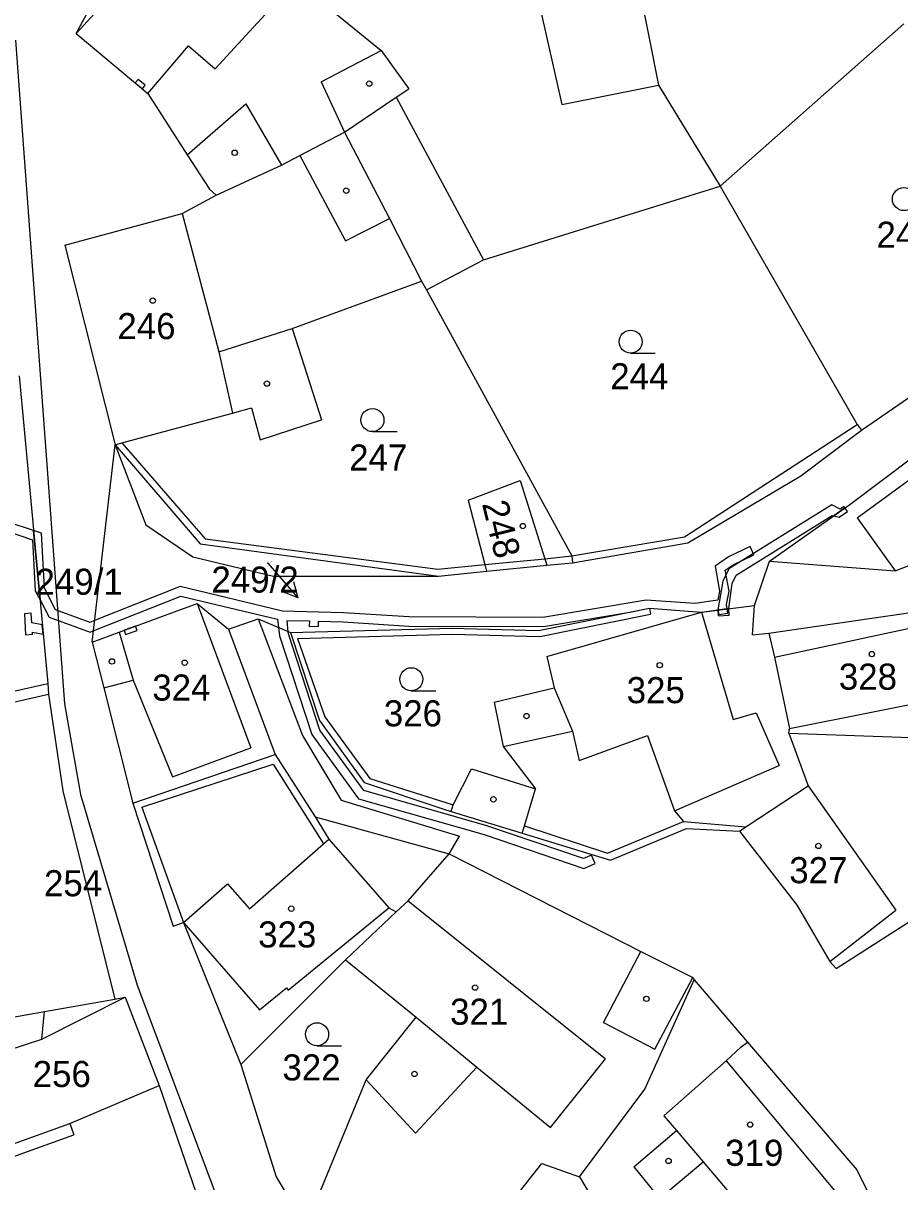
# Model space of a CAD drawing. Extents: x -785744 to -782822, y -1067550 to -1063910.
# Drawn here: x -783849.7 to -783792.6, y -1065395.6 to -1065320.1 of the extents above; entities that cross this region are included whole.
import ezdxf

# ---------------------------------------------------------------- set-up
doc = ezdxf.new("R2010")
doc.units = 0
for name, color, linetype in [('Hranice parcel', 7, 'Continuous'), ('Parcelní čísla', 7, 'Continuous'), ('Pop_ČP_popisy', 7, 'Continuous'), ('Vnitřní kresba', 7, 'Continuous'), ('Věcná břemena k části', 7, 'Continuous'), ('Značky budov', 7, 'Continuous'), ('Značky kultur', 7, 'Continuous')]:
    doc.layers.add(name, color=color, linetype=linetype)

msp = doc.modelspace()

# ---------------------------------------------------------------- linework, layer by layer
at = {"layer": 'Hranice parcel'}
for points in [[(-783846.27, -1065320.75), (-783838.02, -1065311.75)], [(-783810.28, -1065314.14), (-783808.3, -1065324.12)], [(-783831.94, -1065317.32), (-783826.39, -1065321.85)], [(-783804.29, -1065330.7), (-783792.31, -1065320.13)], [(-783846.27, -1065320.75), (-783841.59, -1065324.66)], [(-783830.3, -1065323.9), (-783826.39, -1065321.85)], [(-783830.3, -1065323.9), (-783828.78, -1065327.19)], [(-783841.59, -1065324.66), (-783839.02, -1065328.67)], [(-783808.3, -1065324.12), (-783804.29, -1065330.7)], [(-783831.68, -1065328.7), (-783828.78, -1065327.19)], [(-783828.78, -1065327.19), (-783825.85, -1065332.81)], [(-783839.02, -1065328.67), (-783837.57, -1065330.9)], [(-783837.13, -1065331.29), (-783832.88, -1065329.33)], [(-783832.88, -1065329.33), (-783831.68, -1065328.7)], [(-783819.71, -1065335.52), (-783804.29, -1065330.7)], [(-783804.29, -1065330.7), (-783795.35, -1065346.25)], [(-783839.36, -1065332.49), (-783837.13, -1065331.29)], [(-783837.57, -1065330.9), (-783837.13, -1065331.29)], [(-783847, -1065334.56), (-783839.36, -1065332.49)], [(-783825.85, -1065332.81), (-783823.75, -1065336.9)], [(-783847, -1065334.56), (-783843.73, -1065347.57)], [(-783823.43, -1065337.46), (-783819.71, -1065335.52)], [(-783832.18, -1065339.98), (-783823.75, -1065336.9)], [(-783823.75, -1065336.9), (-783823.43, -1065337.46)], [(-783795.08, -1065346.62), (-783780.58, -1065336.63)], [(-783823.43, -1065337.46), (-783813.95, -1065354.82)], [(-783832.18, -1065339.98), (-783830.28, -1065345.94)], [(-783795.84, -1065351.46), (-783783.28, -1065342.01)], [(-783849.99, -1065343.07), (-783848.11, -1065363.14)], [(-783836.08, -1065345.5), (-783834.83, -1065345.16)], [(-783834.83, -1065345.16), (-783834.26, -1065347.24)], [(-783843.29, -1065347.44), (-783836.08, -1065345.5)], [(-783834.26, -1065347.24), (-783830.28, -1065345.94)], [(-783799.03, -1065349.59), (-783795.08, -1065346.62)], [(-783795.35, -1065346.25), (-783795.08, -1065346.62)], [(-783843.73, -1065347.57), (-783843.29, -1065347.44)], [(-783845.23, -1065360.44), (-783843.73, -1065347.57)], [(-783843.73, -1065347.57), (-783838.18, -1065354.02)], [(-783843.73, -1065347.57), (-783841.73, -1065352.79)], [(-783806.39, -1065353.97), (-783799.03, -1065349.59)], [(-783820.72, -1065351.18), (-783817.32, -1065349.91)], [(-783817.32, -1065349.91), (-783815.72, -1065355)], [(-783820.72, -1065351.18), (-783819.62, -1065355.37)], [(-783801.06, -1065355.17), (-783795.84, -1065351.46)], [(-783841.73, -1065352.79), (-783838.66, -1065354.88)], [(-783838.18, -1065354.02), (-783822.64, -1065356.14)], [(-783813.91, -1065355.27), (-783806.39, -1065353.97)], [(-783792.88, -1065355.8), (-783788.73, -1065354.19)], [(-783838.66, -1065354.88), (-783833.39, -1065356.13)], [(-783815.72, -1065355), (-783815.58, -1065355.43)], [(-783813.95, -1065354.82), (-783813.91, -1065355.27)], [(-783819.62, -1065355.37), (-783819.51, -1065355.81)], [(-783819.51, -1065355.81), (-783815.58, -1065355.43)], [(-783815.58, -1065355.43), (-783813.91, -1065355.27)], [(-783802.04, -1065358.04), (-783801.06, -1065355.17)], [(-783801.06, -1065355.17), (-783792.88, -1065355.8)], [(-783833.39, -1065356.13), (-783822.64, -1065356.14)], [(-783822.64, -1065356.14), (-783819.51, -1065355.81)], [(-783843.47, -1065359.78), (-783838.37, -1065357.92)], [(-783838.37, -1065357.92), (-783836.34, -1065359.59)], [(-783805.5, -1065358.48), (-783802.04, -1065358.04)], [(-783802.18, -1065359.97), (-783802.04, -1065358.04)], [(-783816.13, -1065359.69), (-783808.9, -1065358.23)], [(-783815.59, -1065361.37), (-783805.5, -1065358.48)], [(-783808.9, -1065358.23), (-783805.5, -1065358.48)], [(-783801.11, -1065359.86), (-783789.03, -1065358.1)], [(-783836.34, -1065359.59), (-783834.4, -1065358.91)], [(-783834.4, -1065358.91), (-783832.29, -1065359.82)], [(-783832.29, -1065359.82), (-783821.78, -1065359.52)], [(-783821.78, -1065359.52), (-783816.13, -1065359.69)], [(-783845.23, -1065360.44), (-783843.47, -1065359.78)], [(-783836.34, -1065359.59), (-783833.3, -1065367.77)], [(-783832.29, -1065359.82), (-783830.41, -1065365.56)], [(-783802.18, -1065359.97), (-783801.11, -1065359.86)], [(-783801.11, -1065359.86), (-783800.75, -1065361.42)], [(-783845.23, -1065360.44), (-783844.46, -1065363.41)], [(-783815.59, -1065361.37), (-783815.1, -1065363.43)], [(-783800.75, -1065361.42), (-783799.76, -1065366.08)], [(-783848.11, -1065363.14), (-783848.06, -1065363.84)], [(-783854.85, -1065365.37), (-783848.06, -1065363.84)], [(-783848.06, -1065363.84), (-783847.14, -1065370.13)], [(-783844.46, -1065363.41), (-783842.56, -1065370.93)], [(-783819.01, -1065364.36), (-783815.1, -1065363.43)], [(-783819.01, -1065364.36), (-783818.42, -1065367.25)], [(-783830.41, -1065365.56), (-783827.48, -1065369.59)], [(-783799.82, -1065366.38), (-783799.76, -1065366.08)], [(-783799.82, -1065366.38), (-783798.56, -1065369.81)], [(-783799.82, -1065366.38), (-783787.6, -1065366.8)], [(-783842.56, -1065370.93), (-783833.3, -1065367.77)], [(-783833.3, -1065367.77), (-783830.69, -1065371.84)], [(-783818.42, -1065367.25), (-783816.32, -1065370.01)], [(-783821.69, -1065371.05), (-783820.5, -1065368.71)], [(-783820.5, -1065368.71), (-783816.32, -1065370.01)], [(-783847.14, -1065370.13), (-783843.75, -1065383.73)], [(-783827.48, -1065369.59), (-783822.3, -1065371.34)], [(-783802.61, -1065372.48), (-783798.56, -1065369.81)], [(-783842.56, -1065370.93), (-783839.94, -1065378.96)], [(-783822.3, -1065371.34), (-783821.82, -1065371.48)], [(-783821.82, -1065371.48), (-783821.69, -1065371.05)], [(-783821.82, -1065371.48), (-783817.2, -1065372.89)], [(-783830.69, -1065371.84), (-783829.8, -1065373.29)], [(-783817.2, -1065372.89), (-783811.44, -1065374.66)], [(-783811.44, -1065374.66), (-783806.49, -1065372.6)], [(-783806.49, -1065372.6), (-783803.03, -1065372.76)], [(-783803.03, -1065372.76), (-783802.61, -1065372.48)], [(-783803.03, -1065372.76), (-783799.27, -1065377.62)], [(-783829.8, -1065373.29), (-783825.88, -1065377.76)], [(-783824.63, -1065377.3), (-783821.94, -1065374.25)], [(-783821.94, -1065374.25), (-783809.46, -1065380.62)], [(-783825.4, -1065378.03), (-783824.63, -1065377.3)], [(-783799.27, -1065377.62), (-783797.14, -1065381.27)], [(-783828.7, -1065381.16), (-783825.4, -1065378.03)], [(-783825.88, -1065377.76), (-783825.4, -1065378.03)], [(-783796.72, -1065381.73), (-783791.22, -1065378.19)], [(-783839.94, -1065378.96), (-783839.27, -1065378.72)], [(-783839.27, -1065378.72), (-783835.52, -1065387.99)], [(-783809.46, -1065380.62), (-783806.07, -1065382.3)], [(-783835.52, -1065387.99), (-783828.7, -1065381.16)], [(-783828.7, -1065381.16), (-783824.11, -1065384.9)], [(-783797.14, -1065381.27), (-783796.72, -1065381.73)], [(-783809.19, -1065389.59), (-783805.99, -1065382.45)], [(-783806.07, -1065382.3), (-783805.99, -1065382.45)], [(-783805.99, -1065382.45), (-783802.5, -1065386.52)], [(-783848.32, -1065384.53), (-783843.75, -1065383.73)], [(-783843.75, -1065383.73), (-783843.06, -1065383.6)], [(-783843.06, -1065383.6), (-783840.85, -1065389.36)], [(-783851.39, -1065385.06), (-783848.32, -1065384.53)], [(-783848.51, -1065386.33), (-783848.32, -1065384.53)], [(-783827.35, -1065388.98), (-783824.11, -1065384.9)], [(-783852.98, -1065387.78), (-783848.51, -1065386.33)], [(-783802.92, -1065386.84), (-783802.5, -1065386.52)], [(-783802.5, -1065386.52), (-783795.38, -1065394.86)], [(-783803.9, -1065387.75), (-783802.92, -1065386.84)], [(-783835.52, -1065387.99), (-783833.22, -1065395.31)], [(-783803.9, -1065387.75), (-783796.83, -1065396.2)], [(-783831.29, -1065398.55), (-783827.35, -1065388.98)], [(-783846.68, -1065391.83), (-783840.85, -1065389.36)], [(-783840.85, -1065389.36), (-783837.73, -1065398.45)], [(-783813.46, -1065395.3), (-783809.19, -1065389.59)], [(-783846.68, -1065391.83), (-783846.41, -1065392.56)], [(-783850.7, -1065394.11), (-783846.41, -1065392.56)], [(-783808.23, -1065396.72), (-783805.4, -1065394.32)], [(-783805.4, -1065394.32), (-783800.95, -1065399.58)], [(-783818.16, -1065397.3), (-783815.9, -1065394.43)], [(-783815.9, -1065394.43), (-783813.46, -1065395.3)], [(-783795.38, -1065394.86), (-783791.41, -1065402.84)], [(-783833.22, -1065395.31), (-783831.29, -1065398.55)], [(-783813.46, -1065395.3), (-783809.83, -1065401.41)]]:
    msp.add_lwpolyline(points, dxfattribs=at)
at = {"layer": 'Pop_ČP_popisy'}
msp.add_line((-783833.78, -1065355.3), (-783831.806, -1065357.559), dxfattribs=at)
for points in [[(-783833.82, -1065355.26), (-783833.78, -1065355.3)], [(-783832.087, -1065356.477), (-783831.806, -1065357.559), (-783832.84, -1065357.135)]]:
    msp.add_lwpolyline(points, dxfattribs=at)
at = {"layer": 'Vnitřní kresba'}
for points in [[(-783816.82, -1065315.53), (-783814.61, -1065325.37)], [(-783837.2, -1065323.06), (-783831.94, -1065317.32)], [(-783846.27, -1065320.75), (-783844.85, -1065318.11)], [(-783850.22, -1065321.18), (-783847.02, -1065364.46)], [(-783841.59, -1065324.66), (-783838.94, -1065321.56)], [(-783838.94, -1065321.56), (-783837.2, -1065323.06)], [(-783826.39, -1065321.85), (-783824.58, -1065324.35)], [(-783825.4, -1065324.91), (-783824.58, -1065324.35)], [(-783814.61, -1065325.37), (-783808.3, -1065324.12)], [(-783839.02, -1065328.67), (-783835.21, -1065325.33)], [(-783835.21, -1065325.33), (-783832.88, -1065329.33)], [(-783828.78, -1065327.19), (-783825.4, -1065324.91)], [(-783825.4, -1065324.91), (-783819.71, -1065335.52)], [(-783831.68, -1065328.7), (-783828.71, -1065334.28)], [(-783839.36, -1065332.49), (-783837.43, -1065339.76)], [(-783828.71, -1065334.28), (-783825.85, -1065332.81)], [(-783837.43, -1065339.76), (-783836.96, -1065341.5)], [(-783836.96, -1065341.5), (-783832.18, -1065339.98)], [(-783836.96, -1065341.5), (-783836.08, -1065345.5)], [(-783795.35, -1065352.34), (-783783.09, -1065343.37)], [(-783806.61, -1065353.58), (-783795.35, -1065346.25)], [(-783843.29, -1065347.44), (-783837.85, -1065353.71)], [(-783795.35, -1065352.34), (-783792.88, -1065355.8)], [(-783837.85, -1065353.71), (-783822.68, -1065355.69)], [(-783813.95, -1065354.82), (-783806.61, -1065353.58)], [(-783819.62, -1065355.37), (-783815.72, -1065355)], [(-783815.72, -1065355), (-783813.95, -1065354.82)], [(-783822.68, -1065355.69), (-783819.62, -1065355.37)], [(-783838.37, -1065357.92), (-783834.87, -1065367.33)], [(-783816.05, -1065360.08), (-783808.82, -1065358.62)], [(-783808.9, -1065358.23), (-783808.82, -1065358.62)], [(-783805.5, -1065358.48), (-783803.44, -1065365.49)], [(-783834.4, -1065358.91), (-783831.5, -1065366.52)], [(-783800.75, -1065361.42), (-783789.9, -1065359.1)], [(-783843.47, -1065359.78), (-783842.54, -1065362.92)], [(-783831.83, -1065360.2), (-783821.76, -1065359.91)], [(-783831.83, -1065360.2), (-783830.05, -1065365.3)], [(-783821.76, -1065359.91), (-783816.05, -1065360.08)], [(-783863.39, -1065366.57), (-783848.11, -1065363.14)], [(-783844.46, -1065363.41), (-783842.54, -1065362.92)], [(-783842.54, -1065362.92), (-783839.98, -1065369.22)], [(-783815.1, -1065363.43), (-783813.9, -1065366.24)], [(-783799.76, -1065366.08), (-783788.86, -1065363.9)], [(-783847.02, -1065364.46), (-783845.98, -1065370.38)], [(-783830.05, -1065365.3), (-783827.12, -1065369.33)], [(-783803.44, -1065365.49), (-783801.94, -1065365.05)], [(-783801.94, -1065365.05), (-783800.44, -1065368.48)], [(-783818.42, -1065367.25), (-783813.9, -1065366.24)], [(-783813.9, -1065366.24), (-783813.48, -1065368.15)], [(-783831.5, -1065366.52), (-783828.99, -1065370.74)], [(-783813.48, -1065368.15), (-783809.03, -1065366.53)], [(-783809.03, -1065366.53), (-783807.26, -1065371.44)], [(-783839.98, -1065369.22), (-783834.87, -1065367.33)], [(-783841.98, -1065371.21), (-783833.43, -1065368.39)], [(-783833.43, -1065368.39), (-783830.14, -1065373.59)], [(-783807.26, -1065371.44), (-783800.44, -1065368.48)], [(-783827.12, -1065369.33), (-783821.69, -1065371.05)], [(-783817.05, -1065372.42), (-783816.32, -1065370.01)], [(-783798.56, -1065369.81), (-783792.84, -1065377.92)], [(-783845.98, -1065370.38), (-783842.28, -1065382.81)], [(-783828.99, -1065370.74), (-783821.27, -1065373.09)], [(-783841.98, -1065371.21), (-783839.27, -1065378.72)], [(-783807.26, -1065371.44), (-783806.68, -1065372.13)], [(-783830.69, -1065371.84), (-783821.94, -1065374.25)], [(-783817.2, -1065372.89), (-783817.05, -1065372.42)], [(-783817.05, -1065372.42), (-783811.63, -1065374.19)], [(-783811.63, -1065374.19), (-783806.68, -1065372.13)], [(-783806.68, -1065372.13), (-783802.61, -1065372.48)], [(-783821.94, -1065374.25), (-783821.27, -1065373.09)], [(-783834.96, -1065377.82), (-783830.14, -1065373.59)], [(-783830.14, -1065373.59), (-783829.8, -1065373.29)], [(-783839.27, -1065378.72), (-783836.41, -1065376.19)], [(-783836.41, -1065376.19), (-783834.96, -1065377.82)], [(-783824.63, -1065377.3), (-783811.76, -1065387.61)], [(-783832.44, -1065383.13), (-783825.88, -1065377.76)], [(-783797.14, -1065381.27), (-783792.84, -1065377.92)], [(-783839.27, -1065378.72), (-783834.31, -1065384.41)], [(-783811.88, -1065385.24), (-783809.46, -1065380.62)], [(-783842.28, -1065382.81), (-783836.83, -1065397.33)], [(-783834.31, -1065384.41), (-783832.56, -1065382.98)], [(-783832.56, -1065382.98), (-783832.44, -1065383.13)], [(-783808.55, -1065386.99), (-783806.07, -1065382.3)], [(-783848.51, -1065386.33), (-783843.06, -1065383.6)], [(-783824.11, -1065384.9), (-783820.14, -1065388.15)], [(-783811.88, -1065385.24), (-783808.55, -1065386.99)], [(-783824.15, -1065392.45), (-783820.14, -1065388.15)], [(-783820.14, -1065388.15), (-783815.34, -1065392.08)], [(-783815.34, -1065392.08), (-783811.76, -1065387.61)], [(-783807.95, -1065391.33), (-783803.9, -1065387.75)], [(-783827.35, -1065388.98), (-783824.15, -1065392.45)], [(-783850.96, -1065393.37), (-783846.68, -1065391.83)], [(-783807.95, -1065391.33), (-783807.13, -1065392.28)], [(-783809.92, -1065394.65), (-783807.13, -1065392.28)], [(-783807.13, -1065392.28), (-783805.4, -1065394.32)], [(-783809.92, -1065394.65), (-783808.23, -1065396.72)]]:
    msp.add_lwpolyline(points, dxfattribs=at)
at = {"layer": 'Věcná břemena k části'}
for points in [[(-783842.22, -1065323.74), (-783842.41, -1065323.97), (-783841.95, -1065324.36)], [(-783841.95, -1065324.36), (-783841.76, -1065324.13), (-783842.22, -1065323.74)], [(-783797, -1065351.48), (-783803.71, -1065355.65)], [(-783796.47, -1065351.77), (-783797, -1065351.48)], [(-783796.15, -1065351.68), (-783796.88, -1065352.2)], [(-783796.88, -1065352.2), (-783796.15, -1065351.68)], [(-783796.52, -1065352.28), (-783795.99, -1065351.93)], [(-783796.21, -1065351.6), (-783796.47, -1065351.77)], [(-783796.15, -1065351.68), (-783796.21, -1065351.6)], [(-783795.99, -1065351.93), (-783796.15, -1065351.68)], [(-783849.05, -1065353.16), (-783850.63, -1065352.63)], [(-783803.24, -1065356.07), (-783796.98, -1065352.18)], [(-783796.98, -1065352.18), (-783796.88, -1065352.2)], [(-783796.88, -1065352.2), (-783796.52, -1065352.28)], [(-783850.83, -1065353.19), (-783849.1, -1065353.77)], [(-783848.62, -1065357.68), (-783849.05, -1065353.16)], [(-783848.52, -1065353.33), (-783849.05, -1065353.16)], [(-783849.05, -1065353.16), (-783848.62, -1065357.68)], [(-783848.33, -1065356.93), (-783848.52, -1065353.33)], [(-783849.1, -1065353.77), (-783848.93, -1065357.09)], [(-783802.34, -1065354.21), (-783803.74, -1065354.87)], [(-783802.08, -1065354.75), (-783802.34, -1065354.21)], [(-783803.74, -1065354.87), (-783804.61, -1065355.49)], [(-783803.44, -1065355.39), (-783802.08, -1065354.75)], [(-783804.61, -1065355.49), (-783804.32, -1065357.12)], [(-783803.71, -1065355.65), (-783804.11, -1065356.47)], [(-783803.95, -1065355.75), (-783803.44, -1065355.39)], [(-783803.7, -1065357.12), (-783803.95, -1065355.75)], [(-783804.11, -1065356.47), (-783804.44, -1065358.34), (-783803.71, -1065358.25)], [(-783803.51, -1065356.61), (-783803.24, -1065356.07)], [(-783848.93, -1065357.09), (-783848.62, -1065357.68)], [(-783847.61, -1065358.33), (-783848.33, -1065356.93)], [(-783839.49, -1065356.82), (-783845.07, -1065359.03)], [(-783832.81, -1065358.41), (-783839.49, -1065356.82)], [(-783804.32, -1065357.12), (-783804.44, -1065357.7)], [(-783803.88, -1065357.98), (-783803.7, -1065357.12)], [(-783803.71, -1065358.25), (-783803.51, -1065356.61)], [(-783848.62, -1065357.68), (-783848.03, -1065358.81)], [(-783845.15, -1065359.71), (-783839.45, -1065357.44)], [(-783839.45, -1065357.44), (-783833.13, -1065358.95)], [(-783809.1, -1065357.7), (-783815.84, -1065358.83)], [(-783805.93, -1065357.91), (-783809.1, -1065357.7)], [(-783804.44, -1065357.7), (-783805.93, -1065357.91)], [(-783803.83, -1065358.27), (-783803.88, -1065357.98)], [(-783849.15, -1065359.17), (-783849.19, -1065358.56), (-783849.64, -1065358.59)], [(-783849.64, -1065358.59), (-783849.56, -1065359.96), (-783849.11, -1065359.93)], [(-783848.03, -1065358.81), (-783845.35, -1065359.79)], [(-783845.35, -1065359.15), (-783847.61, -1065358.33)], [(-783828.84, -1065358.52), (-783832.81, -1065358.41)], [(-783824.57, -1065358.8), (-783828.84, -1065358.52)], [(-783815.84, -1065358.83), (-783824.57, -1065358.8)], [(-783815.8, -1065359.43), (-783810.18, -1065358.49)], [(-783810.18, -1065358.49), (-783808.9, -1065358.23)], [(-783808.9, -1065358.23), (-783805.5, -1065358.48)], [(-783805.5, -1065358.48), (-783804.44, -1065358.34)], [(-783804.16, -1065358.31), (-783804.44, -1065358.34)], [(-783804.16, -1065358.31), (-783804.44, -1065358.34)], [(-783804.44, -1065358.34), (-783804.16, -1065358.31)], [(-783804.44, -1065358.34), (-783804.42, -1065358.73)], [(-783804.44, -1065358.34), (-783804.38, -1065358.64)], [(-783804.42, -1065358.73), (-783803.69, -1065358.69)], [(-783804.38, -1065358.64), (-783803.78, -1065358.56)], [(-783803.71, -1065358.25), (-783804.16, -1065358.31)], [(-783803.83, -1065358.27), (-783804.16, -1065358.31)], [(-783804.16, -1065358.31), (-783803.83, -1065358.27)], [(-783803.78, -1065358.56), (-783803.83, -1065358.27)], [(-783803.69, -1065358.69), (-783803.71, -1065358.25)], [(-783848.41, -1065359.93), (-783848.47, -1065359.31), (-783849.15, -1065359.17)], [(-783845.07, -1065359.03), (-783845.35, -1065359.15)], [(-783842.39, -1065359.39), (-783843.14, -1065359.66)], [(-783842.29, -1065359.67), (-783842.39, -1065359.39)], [(-783833.13, -1065358.95), (-783833.07, -1065359.48)], [(-783833.07, -1065359.48), (-783833.02, -1065360.02)], [(-783832.52, -1065359.02), (-783831.06, -1065359.06)], [(-783832.44, -1065359.76), (-783832.52, -1065359.02)], [(-783831.06, -1065359.06), (-783831.07, -1065359.42)], [(-783831.07, -1065359.42), (-783830.47, -1065359.4)], [(-783830.47, -1065359.4), (-783830.46, -1065359.08)], [(-783830.46, -1065359.08), (-783828.86, -1065359.12)], [(-783828.86, -1065359.12), (-783824.59, -1065359.4)], [(-783824.59, -1065359.4), (-783815.8, -1065359.43)], [(-783849.11, -1065359.93), (-783849.12, -1065359.79), (-783848.41, -1065359.93)], [(-783845.35, -1065359.79), (-783845.15, -1065359.71)], [(-783843.14, -1065359.66), (-783843.04, -1065359.94)], [(-783843.04, -1065359.94), (-783842.29, -1065359.67)], [(-783833.02, -1065360.02), (-783830.91, -1065366.47)], [(-783832.42, -1065359.9), (-783832.44, -1065359.76)], [(-783830.37, -1065366.19), (-783832.42, -1065359.9)], [(-783827.51, -1065370.11), (-783830.37, -1065366.19)], [(-783830.91, -1065366.47), (-783827.85, -1065370.66)], [(-783819.49, -1065372.41), (-783827.51, -1065370.11)], [(-783827.85, -1065370.66), (-783819.67, -1065372.99)], [(-783813.2, -1065374.55), (-783819.49, -1065372.41)], [(-783819.67, -1065372.99), (-783813.18, -1065375.19)], [(-783812.67, -1065374.33), (-783813.2, -1065374.55)], [(-783812.44, -1065374.88), (-783812.67, -1065374.33)], [(-783813.18, -1065375.19), (-783812.44, -1065374.88)]]:
    msp.add_lwpolyline(points, dxfattribs=at)
at = {"layer": 'Značky budov'}
for centre in [(-783827.16, -1065324.02), (-783835.93, -1065328.53), (-783828.66, -1065331), (-783841.27, -1065338.17), (-783833.83, -1065343.58), (-783817.15, -1065352.87), (-783794.4, -1065361.22), (-783843.93, -1065361.7), (-783839.19, -1065361.78), (-783808.22, -1065361.94), (-783816.91, -1065365.26), (-783819.07, -1065370.69), (-783797.88, -1065373.73), (-783832.24, -1065377.82), (-783820.26, -1065382.97), (-783809.09, -1065383.7), (-783824.21, -1065388.6), (-783802.33, -1065391.9), (-783807.65, -1065394.27)]:
    msp.add_circle(centre, 0.175, dxfattribs=at)
at = {"layer": 'Značky kultur'}
for p, q in [((-783810.12, -1065341.6), (-783808.52, -1065341.6)), ((-783826.95, -1065346.71), (-783825.35, -1065346.71)), ((-783824.42, -1065363.61), (-783822.82, -1065363.61)), ((-783830.56, -1065386.76), (-783828.96, -1065386.76))]:
    msp.add_line(p, q, dxfattribs=at)
for centre in [(-783792.31, -1065331.55), (-783810.12, -1065340.85), (-783826.95, -1065345.96), (-783824.42, -1065362.86), (-783830.56, -1065386.01)]:
    msp.add_circle(centre, 0.75, dxfattribs=at)

# ---------------------------------------------------------------- texts
at = {"layer": 'Parcelní čísla'}
for s, height, p in [('240', 1.7, (-783794.1, -1065334.72)), ('246', 1.7, (-783843.58, -1065340.68)), ('244', 1.7, (-783811.45, -1065343.95)), ('247', 1.7, (-783828.47, -1065349.25)), ('249/2', 0.1, (-783833.82, -1065355.26)), ('328', 1.7, (-783796.55, -1065363.54)), ('324', 1.7, (-783841.3, -1065364.25)), ('325', 1.7, (-783810.38, -1065364.42)), ('326', 1.7, (-783826.21, -1065365.93)), ('327', 1.7, (-783799.78, -1065376.16)), ('254', 1.7, (-783848.36, -1065377.01)), ('323', 1.7, (-783834.4, -1065380.35)), ('321', 1.7, (-783821.89, -1065385.39)), ('322', 1.7, (-783832.82, -1065389.02)), ('256', 1.7, (-783849.1, -1065389.45)), ('319', 1.7, (-783803.96, -1065394.59))]:
    msp.add_text(s, height=height, dxfattribs=at).set_placement(p)
msp.add_text('248', height=1.7, rotation=283.73625, dxfattribs=at).set_placement((-783819.82, -1065351.41))
at = {"layer": 'Pop_ČP_popisy'}
for s, p in [('249/1', (-783848.914, -1065357.35)), ('249/2', (-783837.448, -1065357.21))]:
    msp.add_text(s, height=1.7, dxfattribs=at).set_placement(p)

doc.saveas('drawing.dxf')
